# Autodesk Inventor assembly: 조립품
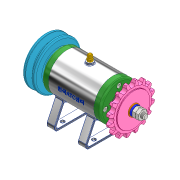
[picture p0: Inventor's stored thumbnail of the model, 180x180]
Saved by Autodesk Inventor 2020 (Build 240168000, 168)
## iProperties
Created: 2021-12
Part Number: 조립품
Document SubType Name: Assembly
Designer: Administrator
Author: Administrator
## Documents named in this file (16)
- C:\Users\Administrator\Desktop\711206V1030\조립품.iam
- C:\Users\Administrator\Desktop\711206V1030\1.본체.ipt
- C:\Users\Administrator\Desktop\711206V1030\축.ipt
- C:\Users\Administrator\Desktop\711206V1030\베어링 6002.ipt
- C:\Users\Administrator\Desktop\711206V1030\커버.ipt
- C:\Users\Administrator\Desktop\711206V1030\오일 실 15 x 25 x 7.ipt
- C:\Users\Administrator\Desktop\711206V1030\볼트 M4 x 12.ipt
- C:\Users\Administrator\Desktop\711206V1030\V벨트풀리.ipt
- C:\Users\Administrator\Desktop\711206V1030\키 3 x 3.ipt
- C:\Users\Administrator\Desktop\711206V1030\스프로킷.ipt
- C:\Users\Administrator\Desktop\711206V1030\스프링와셔 8.ipt
- C:\Users\Administrator\Desktop\711206V1030\와셔 8 x 17.ipt
- C:\Users\Administrator\Desktop\711206V1030\너트 M8.ipt
- C:\Users\Administrator\Desktop\711206V1030\와셔 6 x 11.5.ipt
- C:\Users\Administrator\Desktop\711206V1030\볼트 M6 x 8.ipt
- C:\Users\Administrator\Desktop\711206V1030\니플 M6 x 0.75.ipt
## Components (12 placed, 4 different names)
1. 1.본체:1
2. KS B 2023 6002 - 15 x 32 x 9:1
3. KS B 2023 6002 - 15 x 32 x 9:2
4. ISO 4762 M4 x 12:1
5. ISO 4762 M4 x 12:2
6. ISO 4762 M4 x 12:3
7. ISO 4762 M4 x 12:4
8. ISO 4762 M4 x 12:5
9. ISO 4762 M4 x 12:6
10. ISO 4762 M4 x 12:7
11. ISO 4762 M4 x 12:8
12. V벨트풀리:1 — 각도:1
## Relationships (1: Angle 1)
- 각도:1 [Angle]: V벨트풀리:1
